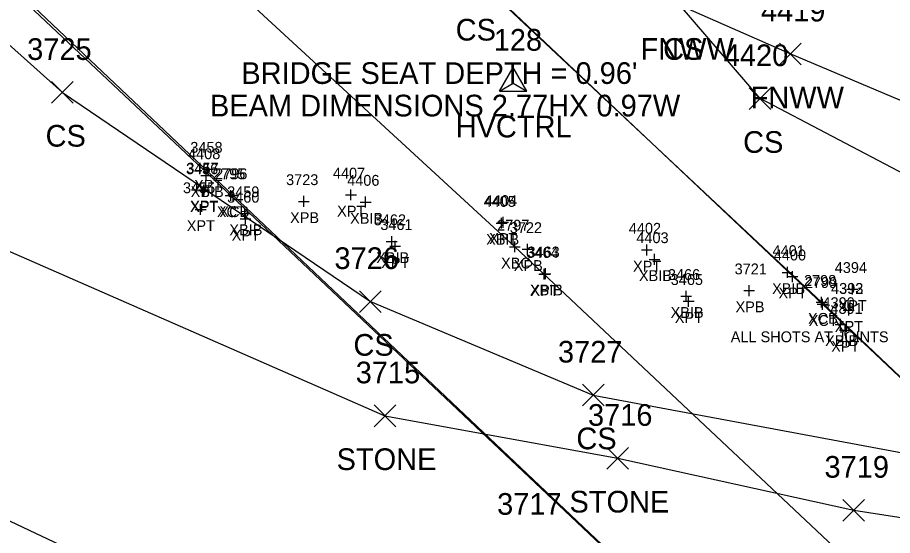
# Model space of a CAD drawing. Extents: x 1647574 to 1652703, y 212895 to 228670.
# Drawn here: x 1648670.8 to 1648751.6, y 227337.9 to 227385.7 of the extents above; entities that cross this region are included whole.
import ezdxf

# ---------------------------------------------------------------- set-up
doc = ezdxf.new("R2010")
doc.units = 0
for name, color, linetype in [('B_A', 7, 'Continuous'), ('B_C', 7, 'Continuous'), ('B_I', 7, 'Continuous'), ('B_TIC', 7, 'Continuous'), ('BDC', 7, 'Continuous'), ('BELB', 7, 'Continuous'), ('C_A', 7, 'Continuous'), ('C_I', 7, 'Continuous'), ('CPSM', 7, 'Continuous'), ('L_A', 7, 'Continuous'), ('L_C', 7, 'Continuous'), ('L_I', 7, 'Continuous'), ('L_TIC', 7, 'Continuous'), ('LASF', 7, 'Continuous'), ('LELB', 7, 'Continuous'), ('LFNC', 7, 'Continuous')]:
    doc.layers.add(name, color=color, linetype=linetype)

msp = doc.modelspace()

# ---------------------------------------------------------------- linework, layer by layer
at = {"layer": 'B_TIC'}
for p, q in [((1648688.43, 227371.691), (1648688.505, 227371.691)), ((1648688.26, 227371.101), (1648688.335, 227371.101)), ((1648688.055, 227369.714), (1648688.131, 227369.714)), ((1648688.071, 227369.776), (1648688.147, 227369.776)), ((1648690.528, 227369.254), (1648690.604, 227369.254)), ((1648690.746, 227369.256), (1648690.821, 227369.256)), ((1648701.626, 227369.312), (1648701.702, 227369.312)), ((1648697.267, 227368.708), (1648697.343, 227368.708)), ((1648702.973, 227368.647), (1648703.049, 227368.647)), ((1648687.749, 227367.963), (1648687.824, 227367.963)), ((1648691.833, 227367.588), (1648691.908, 227367.588)), ((1648691.896, 227367.091), (1648691.971, 227367.091)), ((1648715.657, 227366.78), (1648715.732, 227366.78)), ((1648715.526, 227366.701), (1648715.602, 227366.701)), ((1648705.381, 227365.008), (1648705.457, 227365.008)), ((1648705.702, 227364.565), (1648705.777, 227364.565)), ((1648716.741, 227364.514), (1648716.817, 227364.514)), ((1648717.91, 227364.285), (1648717.986, 227364.285)), ((1648728.935, 227364.223), (1648729.01, 227364.223)), ((1648729.63, 227363.356), (1648729.706, 227363.356)), ((1648719.467, 227361.988), (1648719.542, 227361.988)), ((1648719.565, 227362.037), (1648719.641, 227362.037)), ((1648741.915, 227362.16), (1648741.99, 227362.16)), ((1648742.36, 227361.762), (1648742.435, 227361.762)), ((1648738.378, 227360.476), (1648738.454, 227360.476)), ((1648747.899, 227360.603), (1648747.975, 227360.603)), ((1648732.553, 227359.955), (1648732.628, 227359.955)), ((1648732.787, 227359.493), (1648732.862, 227359.493)), ((1648745.063, 227359.411), (1648745.138, 227359.411)), ((1648745.146, 227359.215), (1648745.221, 227359.215)), ((1648747.556, 227358.667), (1648747.631, 227358.667)), ((1648747.565, 227358.679), (1648747.64, 227358.679)), ((1648746.81, 227357.36), (1648746.886, 227357.36)), ((1648747.222, 227356.83), (1648747.297, 227356.83))]:
    msp.add_line(p, q, dxfattribs=at)
for points in [[(1648687.926, 227371.691), (1648688.926, 227371.691)], [(1648688.256, 227370.601), (1648688.256, 227371.601)], [(1648688.426, 227371.191), (1648688.426, 227372.191)], [(1648687.756, 227371.101), (1648688.756, 227371.101)], [(1648688.052, 227369.214), (1648688.052, 227370.214)], [(1648688.068, 227369.276), (1648688.068, 227370.276)], [(1648687.552, 227369.714), (1648688.552, 227369.714)], [(1648687.568, 227369.776), (1648688.568, 227369.776)], [(1648690.025, 227369.254), (1648691.025, 227369.254)], [(1648690.242, 227369.256), (1648691.242, 227369.256)], [(1648690.525, 227368.754), (1648690.525, 227369.754)], [(1648690.742, 227368.756), (1648690.742, 227369.756)], [(1648697.264, 227368.208), (1648697.264, 227369.208)], [(1648701.123, 227369.312), (1648702.123, 227369.312)], [(1648701.623, 227368.812), (1648701.623, 227369.812)], [(1648702.97, 227368.147), (1648702.97, 227369.147)], [(1648687.745, 227367.463), (1648687.745, 227368.463)], [(1648696.764, 227368.708), (1648697.764, 227368.708)], [(1648702.47, 227368.647), (1648703.47, 227368.647)], [(1648687.245, 227367.963), (1648688.245, 227367.963)], [(1648691.329, 227367.588), (1648692.329, 227367.588)], [(1648691.829, 227367.088), (1648691.829, 227368.088)], [(1648691.892, 227366.591), (1648691.892, 227367.591)], [(1648691.392, 227367.091), (1648692.392, 227367.091)], [(1648715.153, 227366.78), (1648716.153, 227366.78)], [(1648715.523, 227366.201), (1648715.523, 227367.201)], [(1648715.653, 227366.28), (1648715.653, 227367.28)], [(1648715.023, 227366.701), (1648716.023, 227366.701)], [(1648705.378, 227364.508), (1648705.378, 227365.508)], [(1648704.878, 227365.008), (1648705.878, 227365.008)], [(1648705.198, 227364.565), (1648706.198, 227364.565)], [(1648705.698, 227364.065), (1648705.698, 227365.065)], [(1648716.238, 227364.514), (1648717.238, 227364.514)], [(1648716.738, 227364.014), (1648716.738, 227365.014)], [(1648717.907, 227363.785), (1648717.907, 227364.785)], [(1648728.931, 227363.723), (1648728.931, 227364.723)], [(1648717.407, 227364.285), (1648718.407, 227364.285)], [(1648728.431, 227364.223), (1648729.431, 227364.223)], [(1648729.627, 227362.856), (1648729.627, 227363.856)], [(1648729.127, 227363.356), (1648730.127, 227363.356)], [(1648718.963, 227361.988), (1648719.963, 227361.988)], [(1648719.062, 227362.037), (1648720.062, 227362.037)], [(1648719.463, 227361.488), (1648719.463, 227362.488)], [(1648719.562, 227361.537), (1648719.562, 227362.537)], [(1648741.411, 227362.16), (1648742.411, 227362.16)], [(1648741.911, 227361.66), (1648741.911, 227362.66)], [(1648742.356, 227361.262), (1648742.356, 227362.262)], [(1648741.856, 227361.762), (1648742.856, 227361.762)], [(1648747.896, 227360.103), (1648747.896, 227361.103)], [(1648732.549, 227359.455), (1648732.549, 227360.455)], [(1648737.875, 227360.476), (1648738.875, 227360.476)], [(1648738.375, 227359.976), (1648738.375, 227360.976)], [(1648747.396, 227360.603), (1648748.396, 227360.603)], [(1648732.049, 227359.955), (1648733.049, 227359.955)], [(1648732.283, 227359.493), (1648733.283, 227359.493)], [(1648732.783, 227358.993), (1648732.783, 227359.993)], [(1648745.059, 227358.911), (1648745.059, 227359.911)], [(1648745.142, 227358.715), (1648745.142, 227359.715)], [(1648744.559, 227359.411), (1648745.559, 227359.411)], [(1648744.642, 227359.215), (1648745.642, 227359.215)], [(1648747.052, 227358.667), (1648748.052, 227358.667)], [(1648747.061, 227358.679), (1648748.061, 227358.679)], [(1648747.552, 227358.167), (1648747.552, 227359.167)], [(1648747.561, 227358.179), (1648747.561, 227359.179)], [(1648746.807, 227356.86), (1648746.807, 227357.86)], [(1648746.307, 227357.36), (1648747.307, 227357.36)], [(1648747.218, 227356.33), (1648747.218, 227357.33)], [(1648746.718, 227356.83), (1648747.718, 227356.83)]]:
    msp.add_lwpolyline(points, dxfattribs=at)
at = {"layer": 'BDC'}
for points in [[(1648650.624, 227406.773), (1648690.525, 227369.254), (1648733.472, 227328.732), (1648776.312, 227288.32), (1648833.664, 227234.301), (1648891.231, 227180.054), (1648955.856, 227118.961), (1649002.635, 227075.018), (1649045.277, 227034.596)], [(1648651.076, 227406.804), (1648690.742, 227369.256), (1648733.458, 227328.853), (1648776.322, 227288.427), (1648833.713, 227234.413), (1648891.304, 227180.165), (1648955.952, 227119.198), (1649002.814, 227075.033), (1649045.282, 227034.879)], [(1648705.852, 227396.154), (1648745.059, 227359.411), (1648787.916, 227318.711), (1648830.863, 227278.3), (1648888.33, 227224.067), (1648945.958, 227169.85), (1649010.577, 227108.866), (1649057.241, 227064.803), (1649099.962, 227024.603)], [(1648705.902, 227396.256), (1648745.142, 227359.215), (1648788.072, 227318.717), (1648831.078, 227278.232), (1648888.572, 227223.976), (1648945.897, 227169.932), (1649010.764, 227109.119), (1649057.374, 227064.845), (1649100.019, 227024.673)]]:
    msp.add_lwpolyline(points, dxfattribs=at)
at = {"layer": 'BELB'}
msp.add_lwpolyline([(1648676.128, 227401.909), (1648716.738, 227364.514), (1648759.552, 227324.27), (1648803.456, 227283.214), (1648860.317, 227229.513), (1648917.836, 227175.012), (1648982.231, 227114.435), (1649029.643, 227069.952), (1649071.001, 227030.272)], dxfattribs=at)
at = {"layer": 'CPSM'}
for p, q in [((1648715.34, 227378.887), (1648716.59, 227381.052)), ((1648717.84, 227378.887), (1648716.59, 227381.052)), ((1648716.59, 227379.608), (1648716.59, 227381.052)), ((1648715.34, 227378.887), (1648716.59, 227379.608)), ((1648715.34, 227378.887), (1648717.84, 227378.887)), ((1648716.59, 227379.608), (1648716.59, 227379.608)), ((1648716.59, 227379.608), (1648717.84, 227378.887))]:
    msp.add_line(p, q, dxfattribs=at)
at = {"layer": 'L_TIC'}
for points in [[(1648741.16, 227381.305), (1648743.16, 227383.305)], [(1648743.16, 227381.305), (1648741.16, 227383.305)], [(1648673.999, 227377.757), (1648675.999, 227379.757)], [(1648675.999, 227377.757), (1648673.999, 227379.757)], [(1648738.372, 227377.185), (1648740.372, 227379.185)], [(1648740.372, 227377.185), (1648738.372, 227379.185)], [(1648702.409, 227358.468), (1648704.409, 227360.468)], [(1648704.409, 227358.468), (1648702.409, 227360.468)], [(1648722.983, 227349.839), (1648724.983, 227351.839)], [(1648724.983, 227349.839), (1648722.983, 227351.839)], [(1648703.752, 227347.923), (1648705.752, 227349.923)], [(1648705.752, 227347.923), (1648703.752, 227349.923)], [(1648725.242, 227344.003), (1648727.242, 227346.003)], [(1648727.242, 227344.003), (1648725.242, 227346.003)], [(1648747.022, 227339.215), (1648749.022, 227341.215)], [(1648749.022, 227339.215), (1648747.022, 227341.215)]]:
    msp.add_lwpolyline(points, dxfattribs=at)
at = {"layer": 'LASF'}
msp.add_lwpolyline([(1648650.222, 227380.955), (1648665.187, 227366.232), (1648704.752, 227348.923), (1648726.242, 227345.003), (1648748.022, 227340.215), (1648778.691, 227335.468), (1648795.179, 227328.09), (1648829.721, 227323.979), (1648869.231, 227314.255), (1648889.736, 227315.356), (1648906.07, 227312.609), (1648918.662, 227314.372), (1648951.491, 227306.349), (1648977.567, 227292.251), (1648987.29, 227278.611), (1648987.249, 227274.742)], dxfattribs=at)
at = {"layer": 'LELB'}
for points in [[(1648802.54, 227345.24), (1648786.114, 227347.555), (1648759.416, 227367.691), (1648739.372, 227378.185), (1648731.995, 227386.766), (1648727.058, 227392.46), (1648712.321, 227394.449), (1648712.844, 227388.544), (1648680.723, 227395.92), (1648651.479, 227401.026)], [(1648655.911, 227395.863), (1648674.999, 227378.757), (1648703.409, 227359.468), (1648723.983, 227350.839), (1648755.179, 227345.024), (1648824.556, 227329.555), (1648858.755, 227322.284), (1648879.14, 227320.58)], [(1648624.782, 227367.39), (1648661.563, 227343.255), (1648687.991, 227330.789), (1648710.881, 227324.59), (1648732.4, 227320.11), (1648758.291, 227314.941), (1648781.981, 227308.526), (1648826.946, 227303.501), (1648863.734, 227300.174), (1648907.545, 227292.016), (1648945.167, 227284.729), (1648987.249, 227274.742), (1649006.387, 227273.993), (1649032.821, 227270.544), (1649043.18, 227273.015), (1649036.389, 227297.452)]]:
    msp.add_lwpolyline(points, dxfattribs=at)
at = {"layer": 'LFNC'}
msp.add_lwpolyline([(1648808.268, 227354.839), (1648796.625, 227359.528), (1648772.512, 227369.49), (1648742.16, 227382.305), (1648731.995, 227386.766), (1648712.321, 227394.449)], dxfattribs=at)

# ---------------------------------------------------------------- texts
at = {"layer": 'B_A'}
for s, p in [('XBIB', (1648686.827, 227369.101)), ('XPT', (1648687.147, 227369.691)), ('XPT', (1648686.772, 227367.714)), ('XPT', (1648686.788, 227367.776)), ('XCT', (1648689.245, 227367.254)), ('XCB', (1648689.478, 227367.256)), ('XPB', (1648696, 227366.708)), ('XPT', (1648700.343, 227367.312)), ('XBIB', (1648701.541, 227366.647)), ('XPT', (1648686.466, 227365.963)), ('XBIB', (1648690.4, 227365.588)), ('XPT', (1648690.613, 227365.091)), ('XBIB', (1648714.094, 227364.701)), ('XPT', (1648714.374, 227364.78)), ('XBIB', (1648703.949, 227363.008)), ('XPT', (1648704.419, 227362.565)), ('XBC', (1648715.474, 227362.514)), ('XPB', (1648716.643, 227362.285)), ('XPT', (1648727.652, 227362.223)), ('XBIB', (1648728.198, 227361.356)), ('XBIB', (1648740.482, 227360.16)), ('XBIB', (1648718.133, 227360.037)), ('XPT', (1648718.184, 227359.988)), ('XPT', (1648741.077, 227359.762)), ('XPB', (1648737.111, 227358.476)), ('XPT', (1648746.616, 227358.603)), ('XBIB', (1648731.12, 227357.955)), ('XPT', (1648731.504, 227357.493)), ('XCB', (1648743.795, 227357.411)), ('XCT', (1648743.863, 227357.215)), ('XPT', (1648746.273, 227356.667)), ('XPT', (1648746.282, 227356.679)), ('XBIB', (1648745.378, 227355.36)), ('XPT', (1648745.939, 227354.83))]:
    msp.add_text(s, height=1, dxfattribs=at).set_placement(p)
at = {"layer": 'B_C'}
msp.add_text('ALL SHOTS AT JOINTS', height=1, dxfattribs=at).set_placement((1648736.67, 227355.715))
at = {"layer": 'B_I'}
for s, p in [('3458', (1648686.796, 227373.191)), ('4408', (1648686.587, 227372.601)), ('3456', (1648686.394, 227371.214)), ('3457', (1648686.438, 227371.276)), ('2795', (1648688.895, 227370.754)), ('2796', (1648689.085, 227370.756)), ('4407', (1648699.954, 227370.812)), ('3723', (1648695.634, 227370.208)), ('4406', (1648701.273, 227370.147)), ('3455', (1648686.116, 227369.463)), ('3459', (1648690.196, 227369.088)), ('3460', (1648690.195, 227368.591)), ('4405', (1648713.854, 227368.201)), ('4404', (1648713.984, 227368.28)), ('3462', (1648703.724, 227366.508)), ('3461', (1648704.328, 227366.065)), ('2797', (1648715.108, 227366.014)), ('3722', (1648716.277, 227365.785)), ('4402', (1648727.262, 227365.723)), ('4403', (1648727.957, 227364.856)), ('3464', (1648717.81, 227363.488)), ('3463', (1648717.908, 227363.537)), ('4401', (1648740.526, 227363.66)), ('4400', (1648740.644, 227363.262)), ('3721', (1648737.028, 227361.976)), ('4394', (1648746.266, 227362.103)), ('3466', (1648730.868, 227361.455)), ('3465', (1648731.13, 227360.993)), ('2798', (1648743.429, 227360.911)), ('2799', (1648743.508, 227360.715)), ('4392', (1648745.922, 227360.167)), ('4393', (1648745.931, 227360.179)), ('4390', (1648745.134, 227358.86)), ('4391', (1648745.872, 227358.33))]:
    msp.add_text(s, height=1, dxfattribs=at).set_placement(p)
at = {"layer": 'C_A'}
msp.add_text('HVCTRL', height=2, dxfattribs=at).set_placement((1648711.283, 227374.608))
at = {"layer": 'C_I'}
msp.add_text('128', height=2, dxfattribs=at).set_placement((1648714.795, 227382.608))
at = {"layer": 'L_A'}
for s, p in [('CS', (1648711.285, 227383.544)), ('FNWW', (1648728.342, 227381.766)), ('CS', (1648730.436, 227381.766)), ('FNWW', (1648738.506, 227377.305)), ('CS', (1648673.44, 227373.757)), ('CS', (1648737.813, 227373.185)), ('CS', (1648701.85, 227354.468)), ('CS', (1648722.424, 227345.839)), ('STONE', (1648700.295, 227343.923)), ('STONE', (1648721.786, 227340.003))]:
    msp.add_text(s, height=2, dxfattribs=at).set_placement(p)
at = {"layer": 'L_C'}
for s, p in [("BRIDGE SEAT DEPTH = 0.96'", (1648691.506, 227379.544)), ('BEAM DIMENSIONS 2.77HX 0.97W', (1648688.609, 227376.544))]:
    msp.add_text(s, height=2, dxfattribs=at).set_placement(p)
at = {"layer": 'L_I'}
for s, p in [('4419', (1648739.459, 227385.305)), ('3725', (1648671.739, 227381.757)), ('4420', (1648736.026, 227381.185)), ('3726', (1648700.094, 227362.468)), ('3727', (1648720.724, 227353.839)), ('3715', (1648702.059, 227351.923)), ('3716', (1648723.495, 227348.003)), ('3719', (1648745.321, 227343.215)), ('3717', (1648715.107, 227339.794))]:
    msp.add_text(s, height=2, dxfattribs=at).set_placement(p)

doc.saveas('drawing.dxf')
